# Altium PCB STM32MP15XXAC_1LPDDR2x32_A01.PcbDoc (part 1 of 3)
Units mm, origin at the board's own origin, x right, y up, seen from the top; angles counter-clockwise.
Board outline 89 x 120 mm, 6 copper layers (Top Layer, Signal Layer 1, Signal Layer 2, Signal Layer 3, Signal Layer 4, Bottom Layer), stack 1.556 mm thick; 87 components, 99 nets, 861 pads, 454 vias.
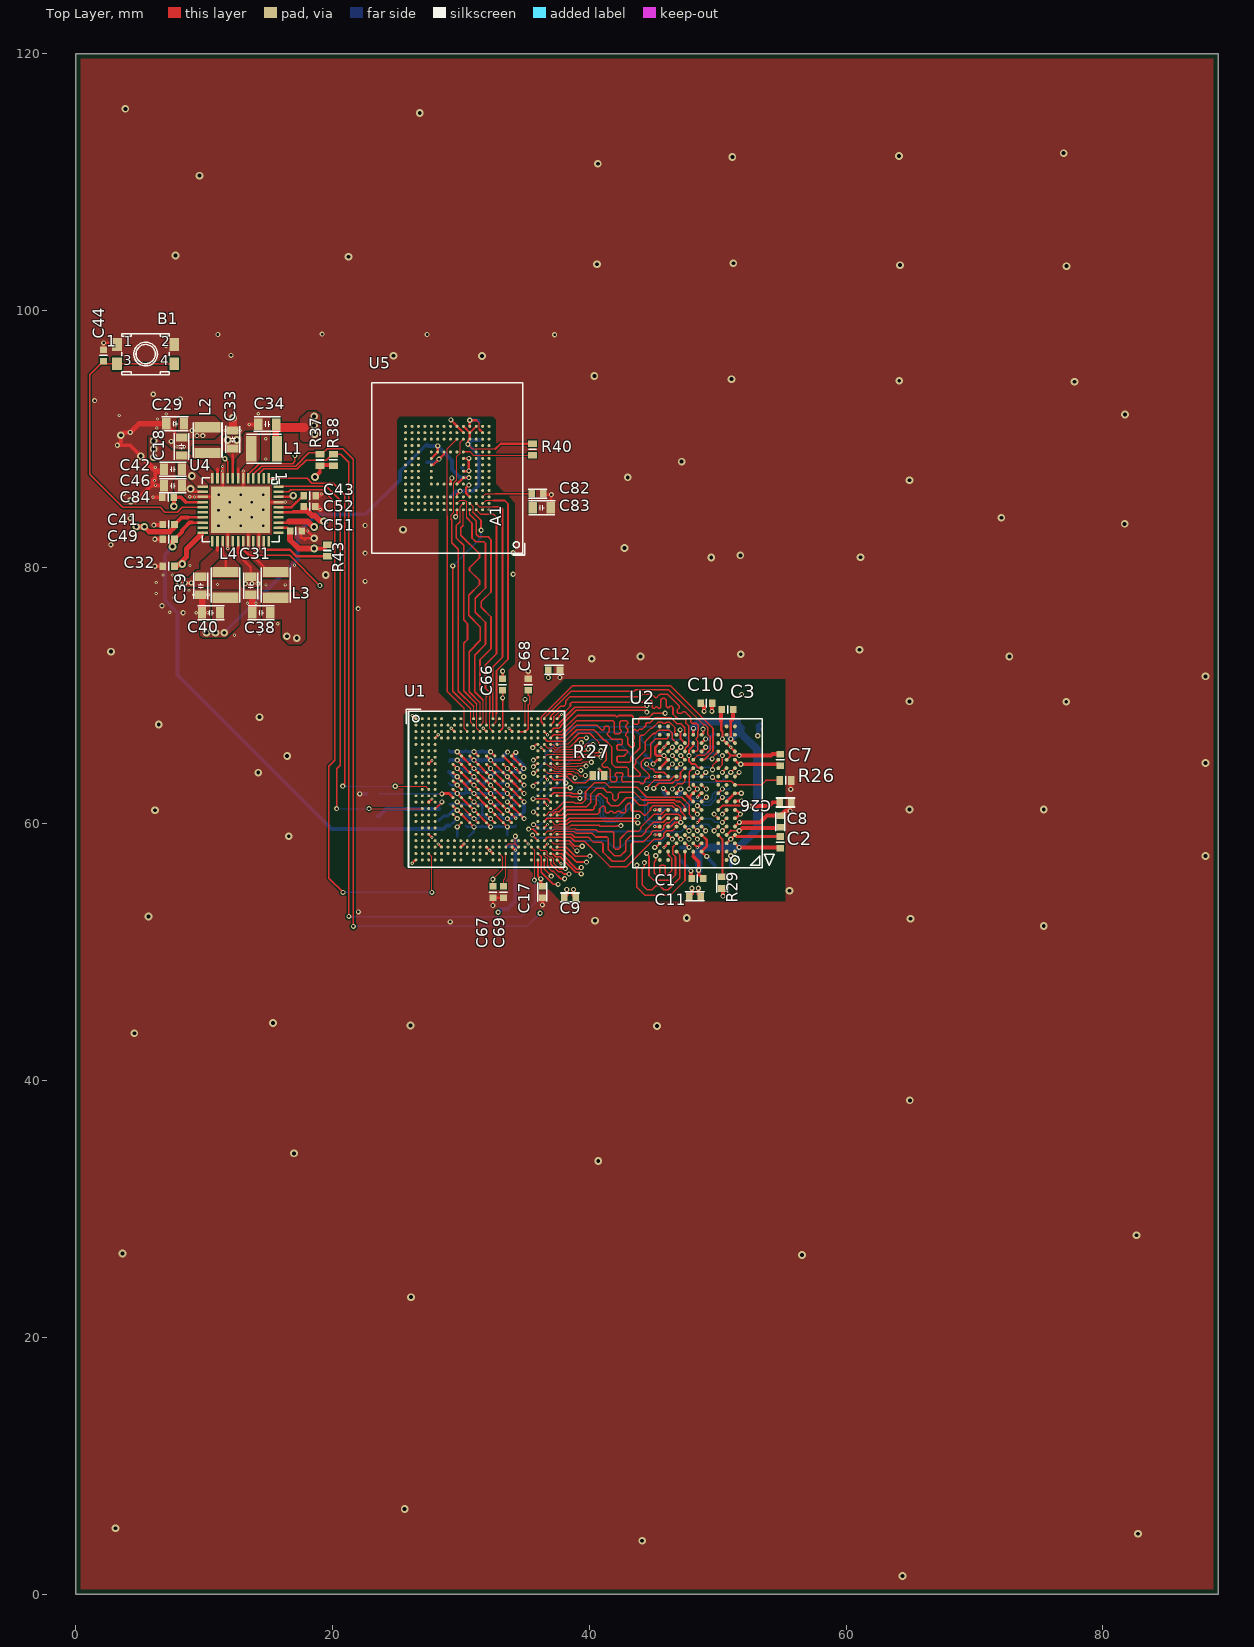
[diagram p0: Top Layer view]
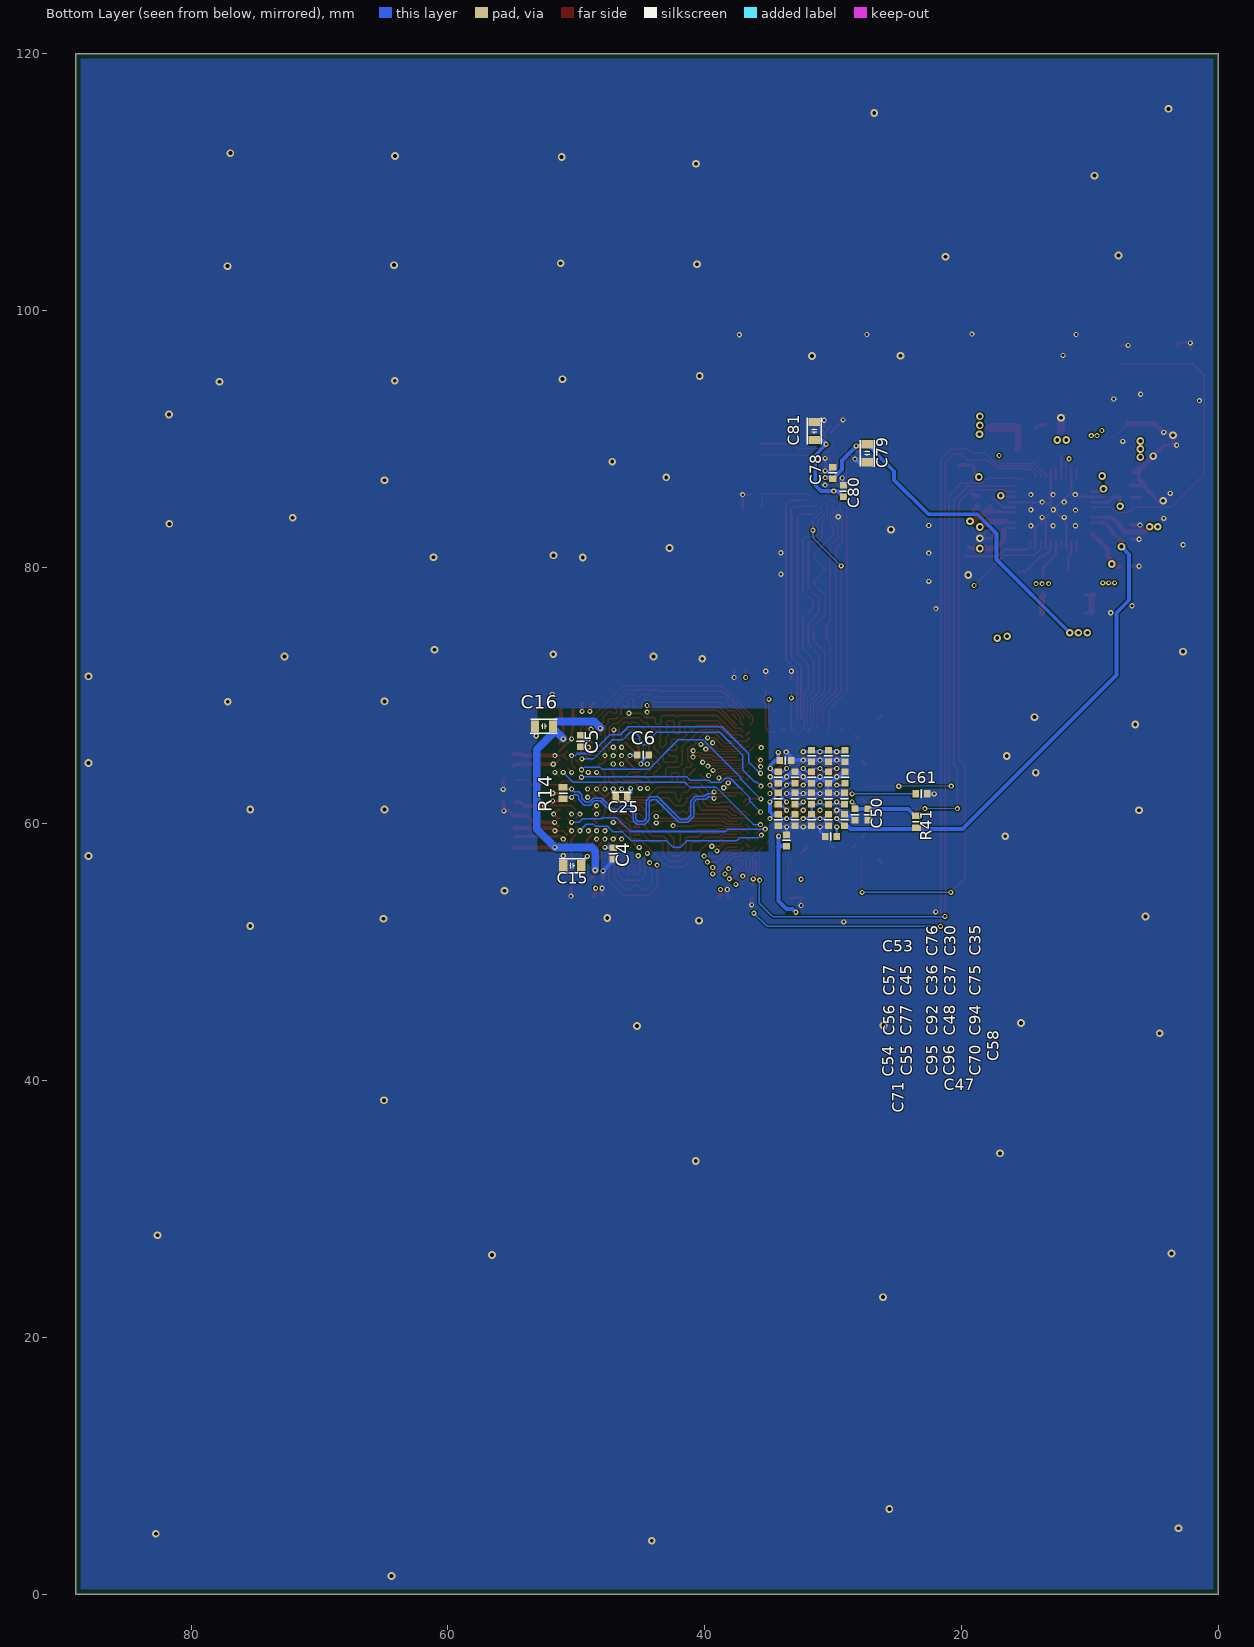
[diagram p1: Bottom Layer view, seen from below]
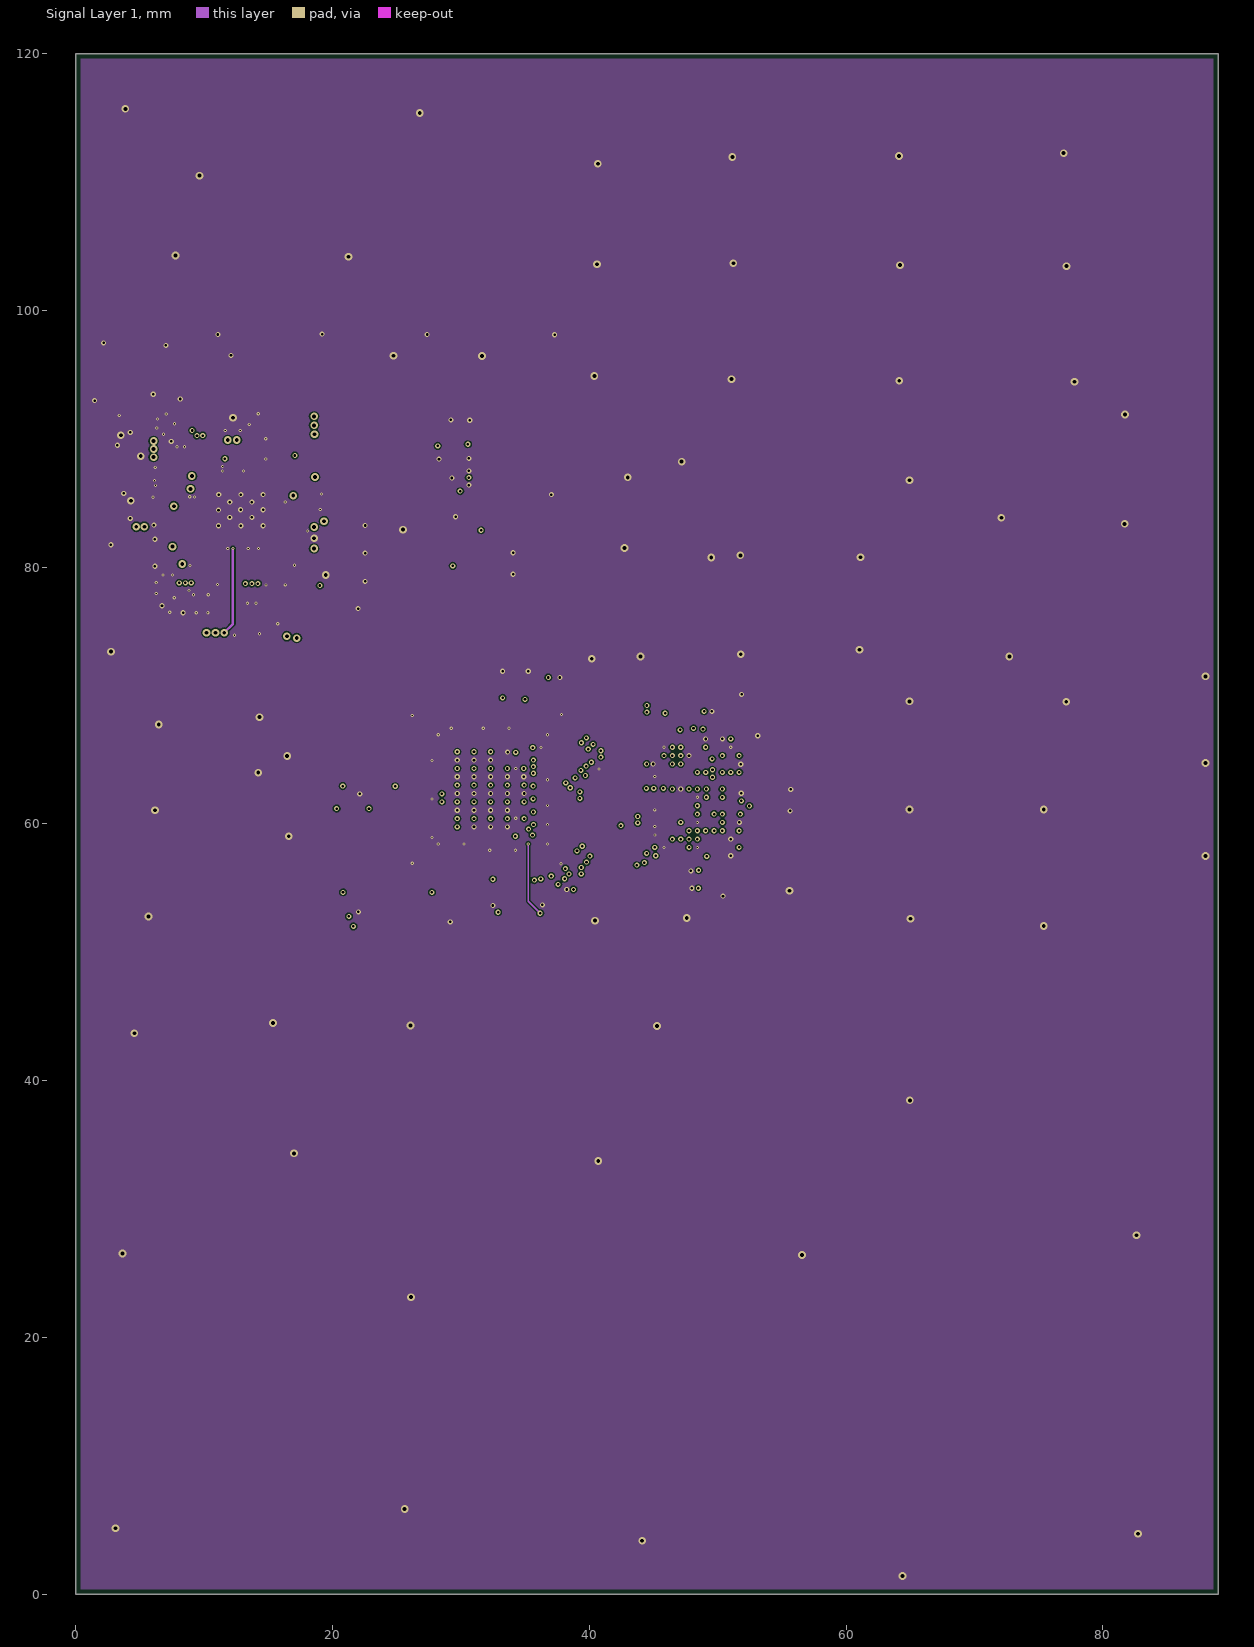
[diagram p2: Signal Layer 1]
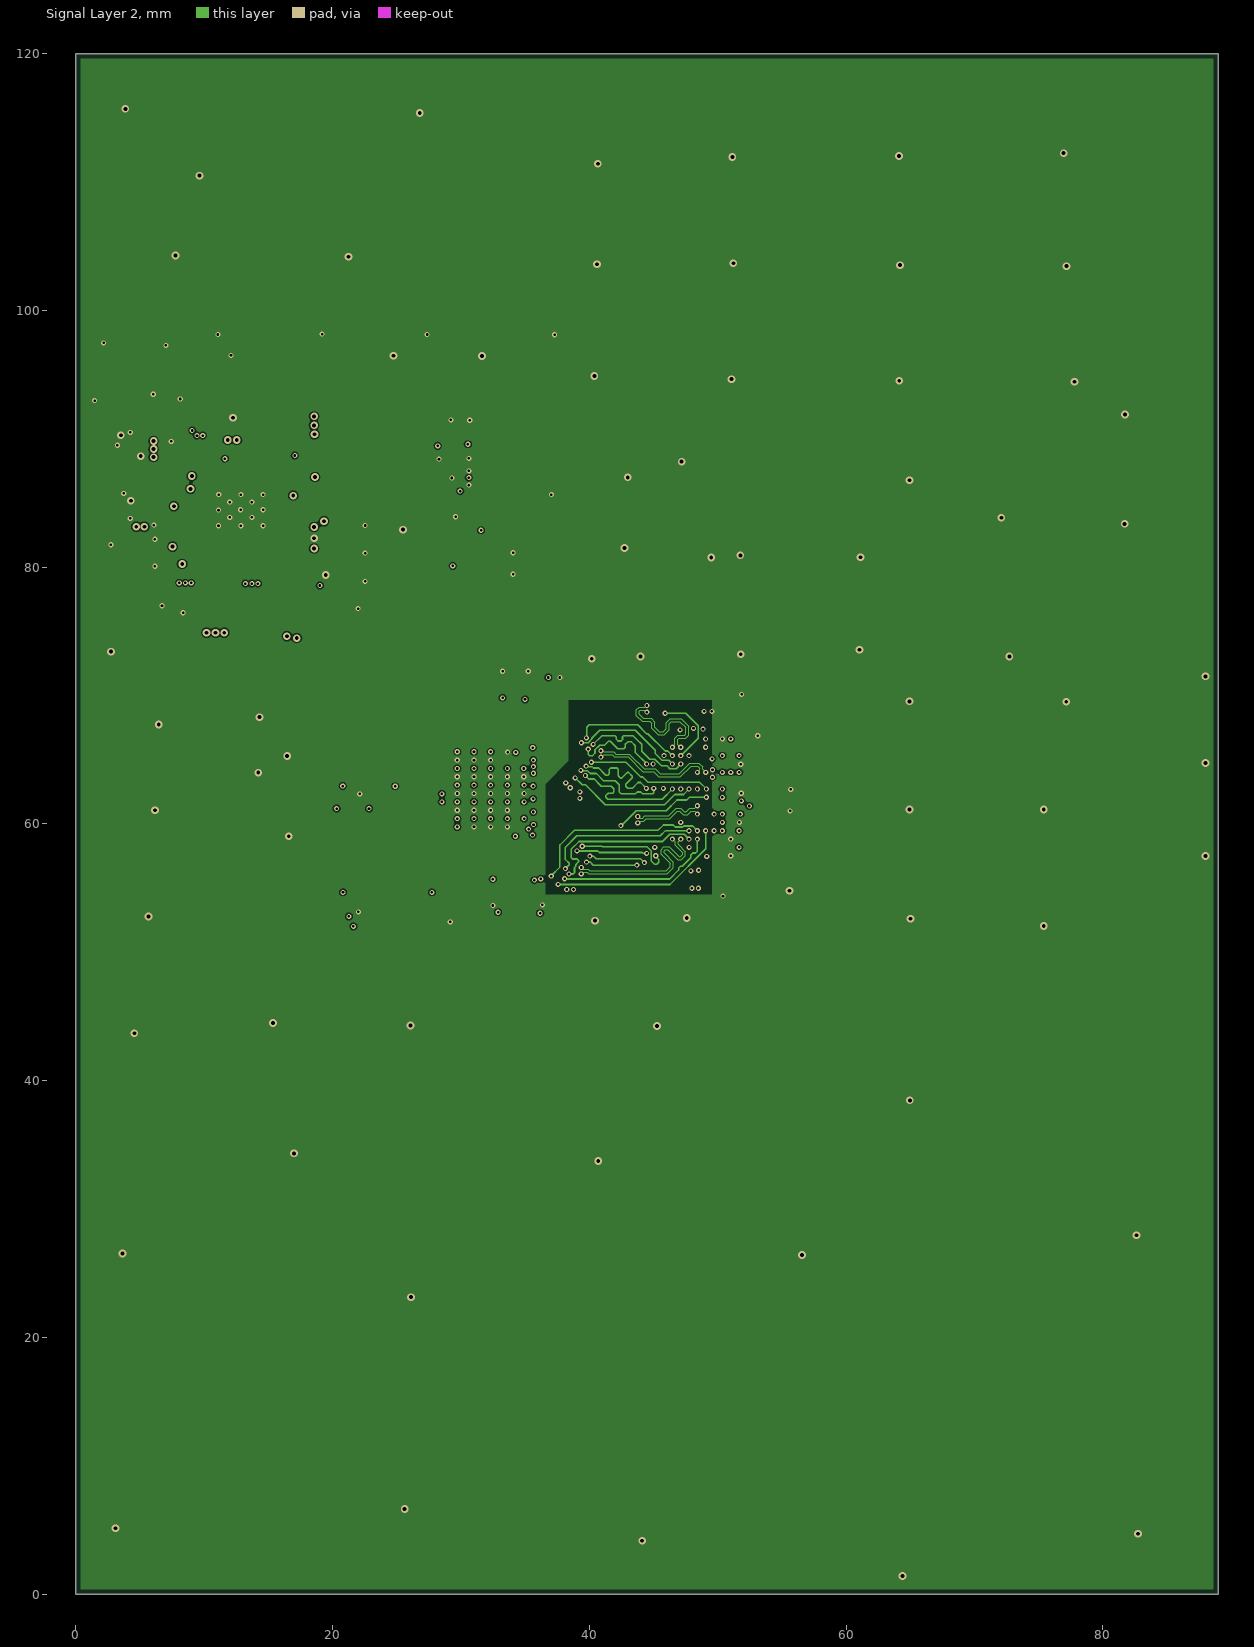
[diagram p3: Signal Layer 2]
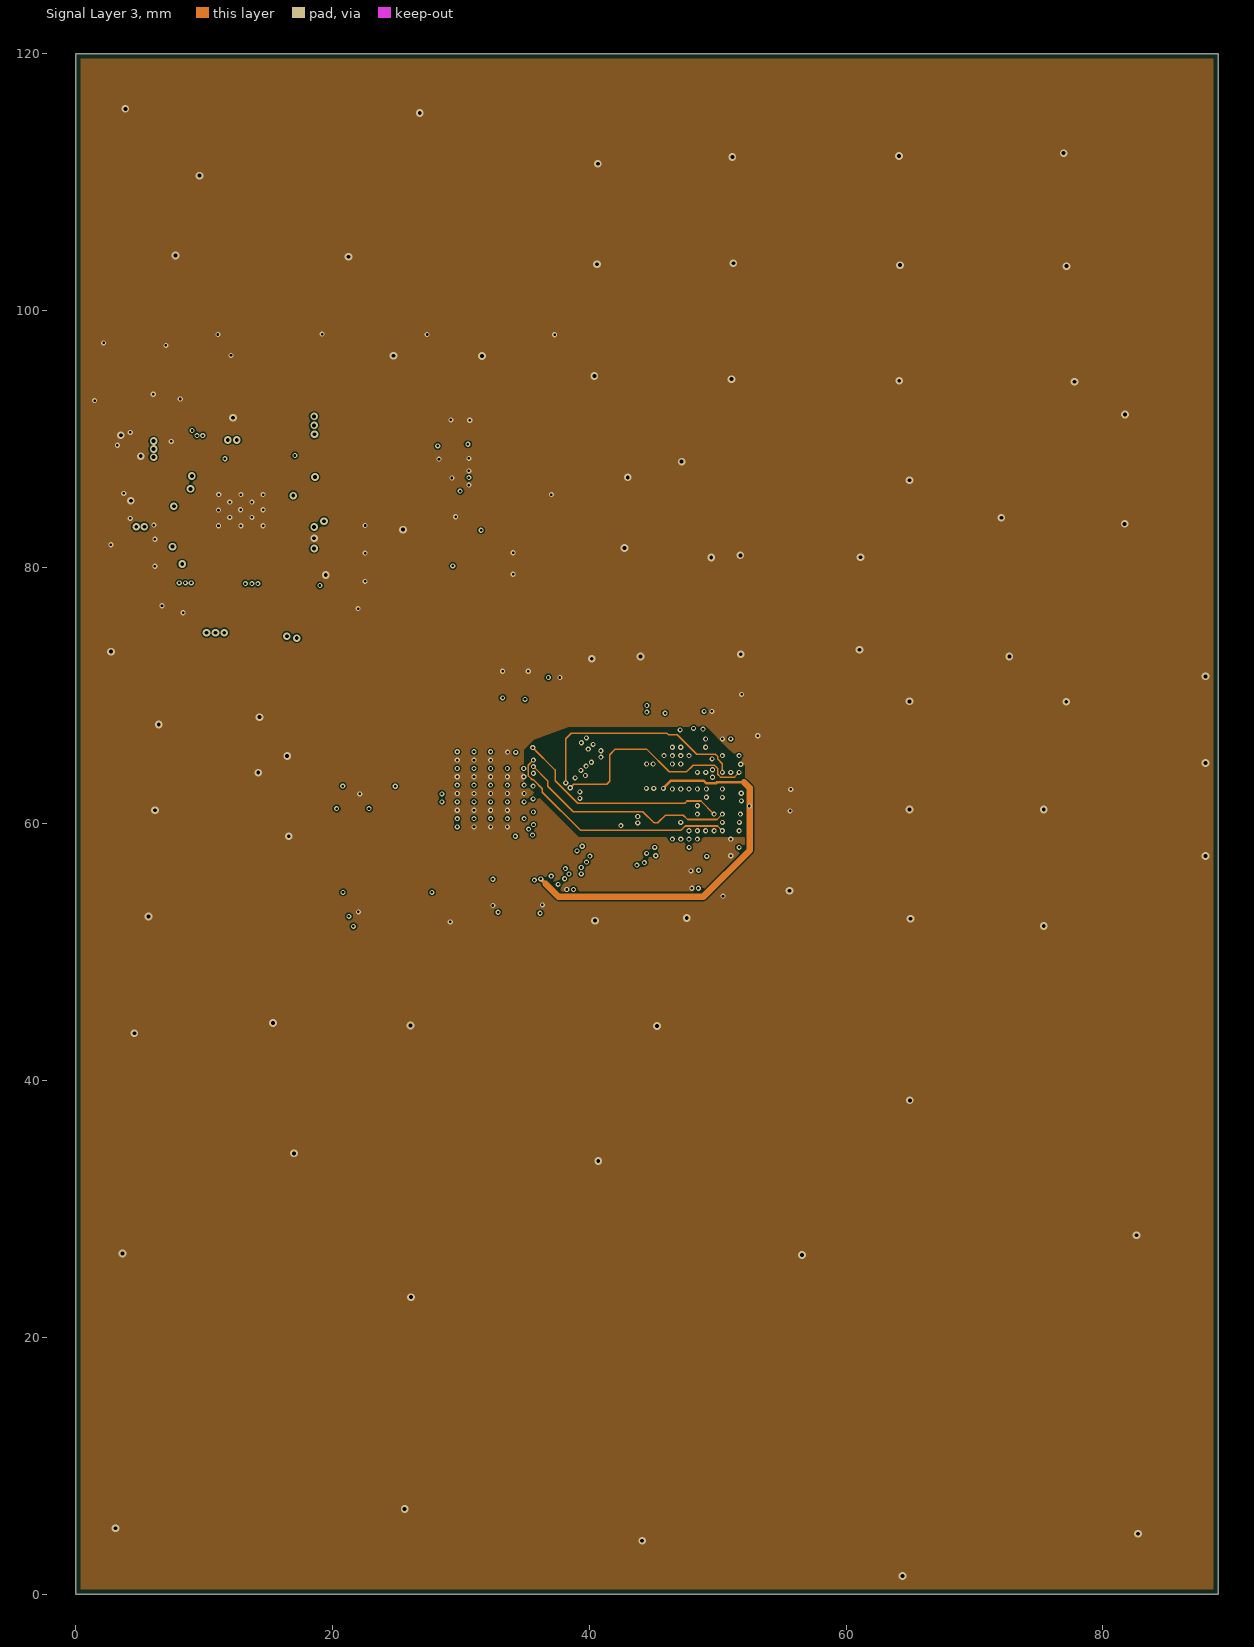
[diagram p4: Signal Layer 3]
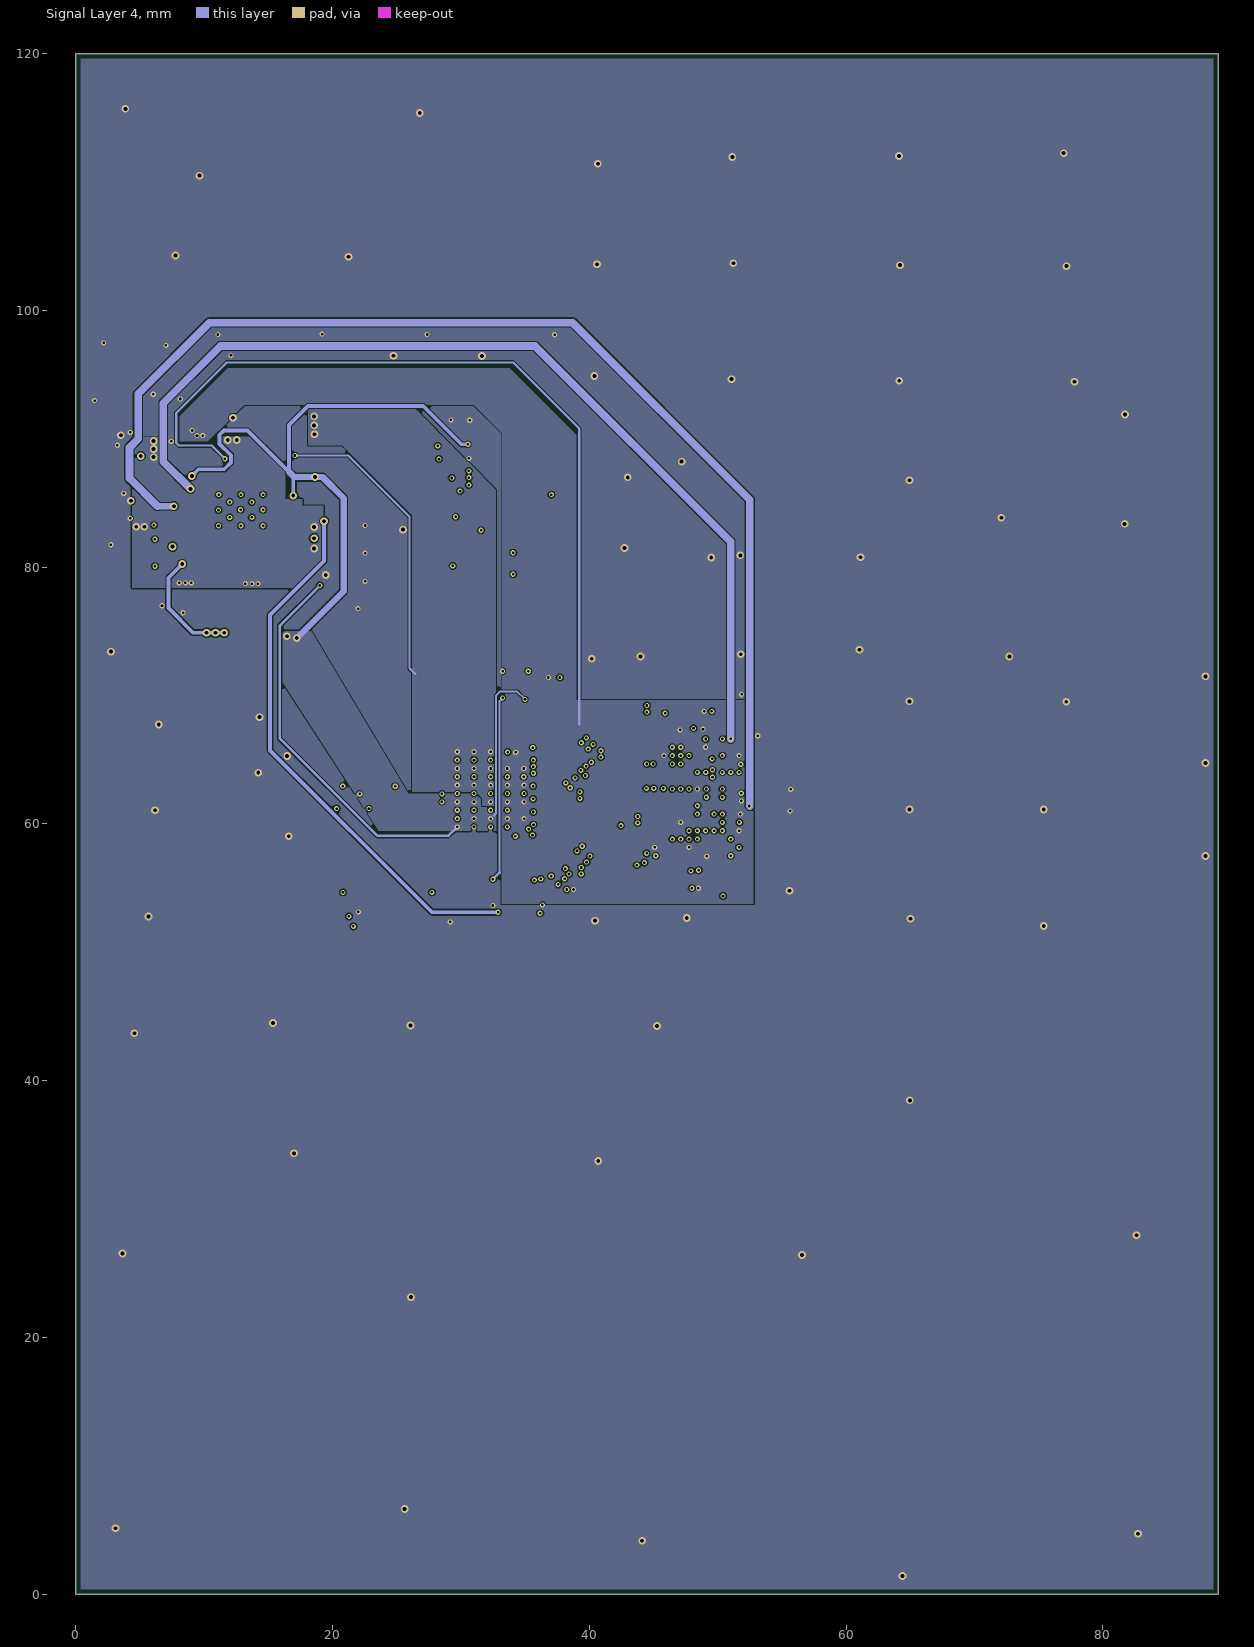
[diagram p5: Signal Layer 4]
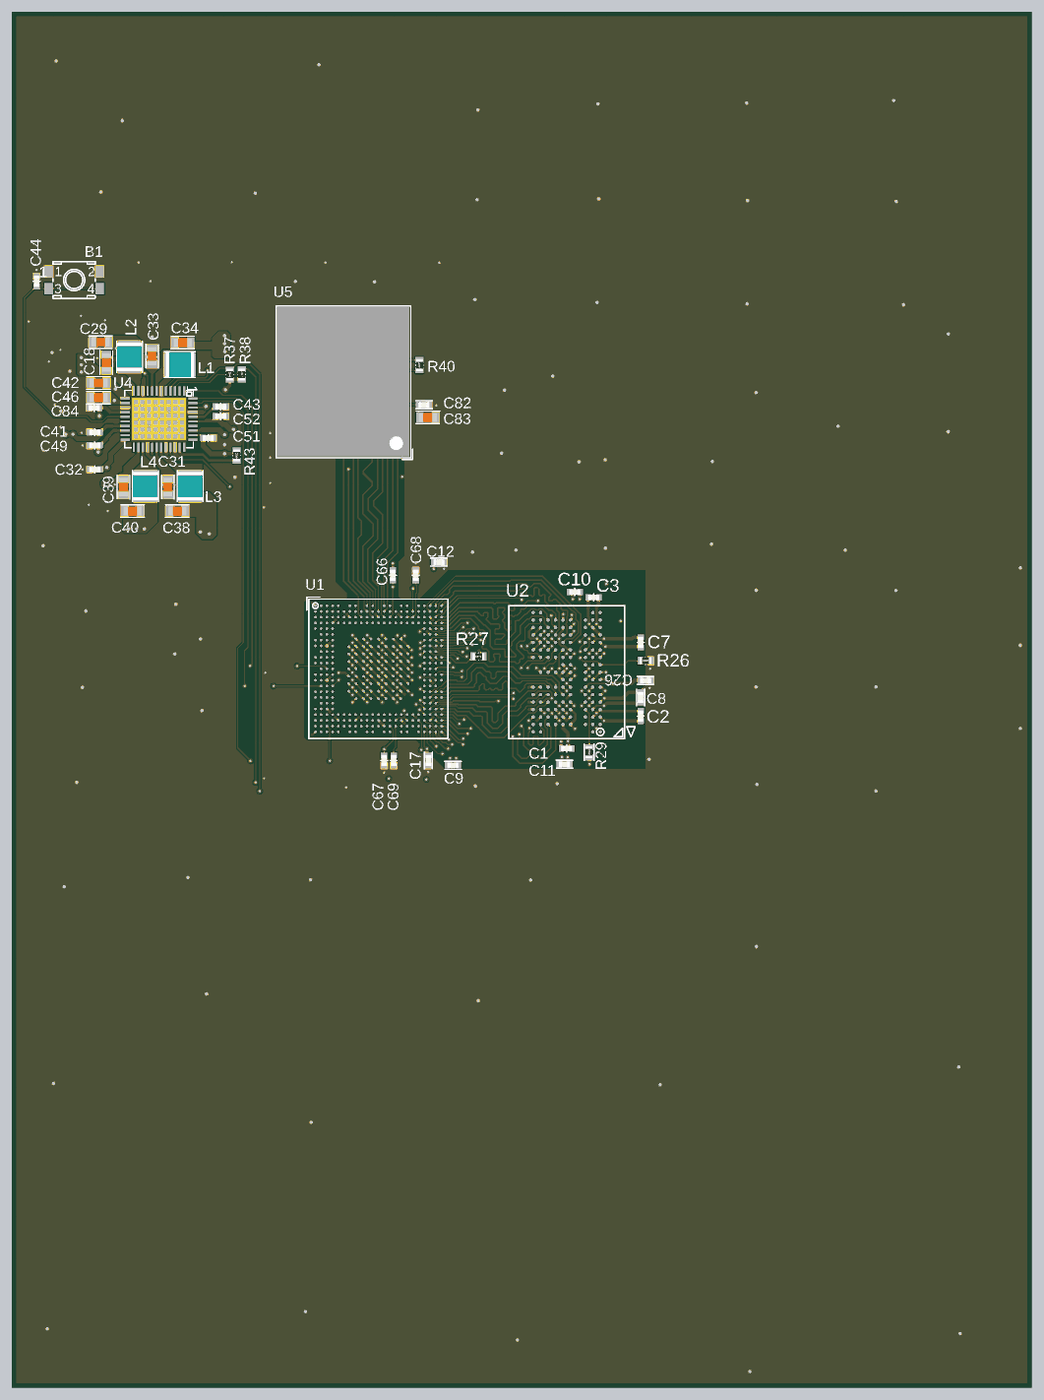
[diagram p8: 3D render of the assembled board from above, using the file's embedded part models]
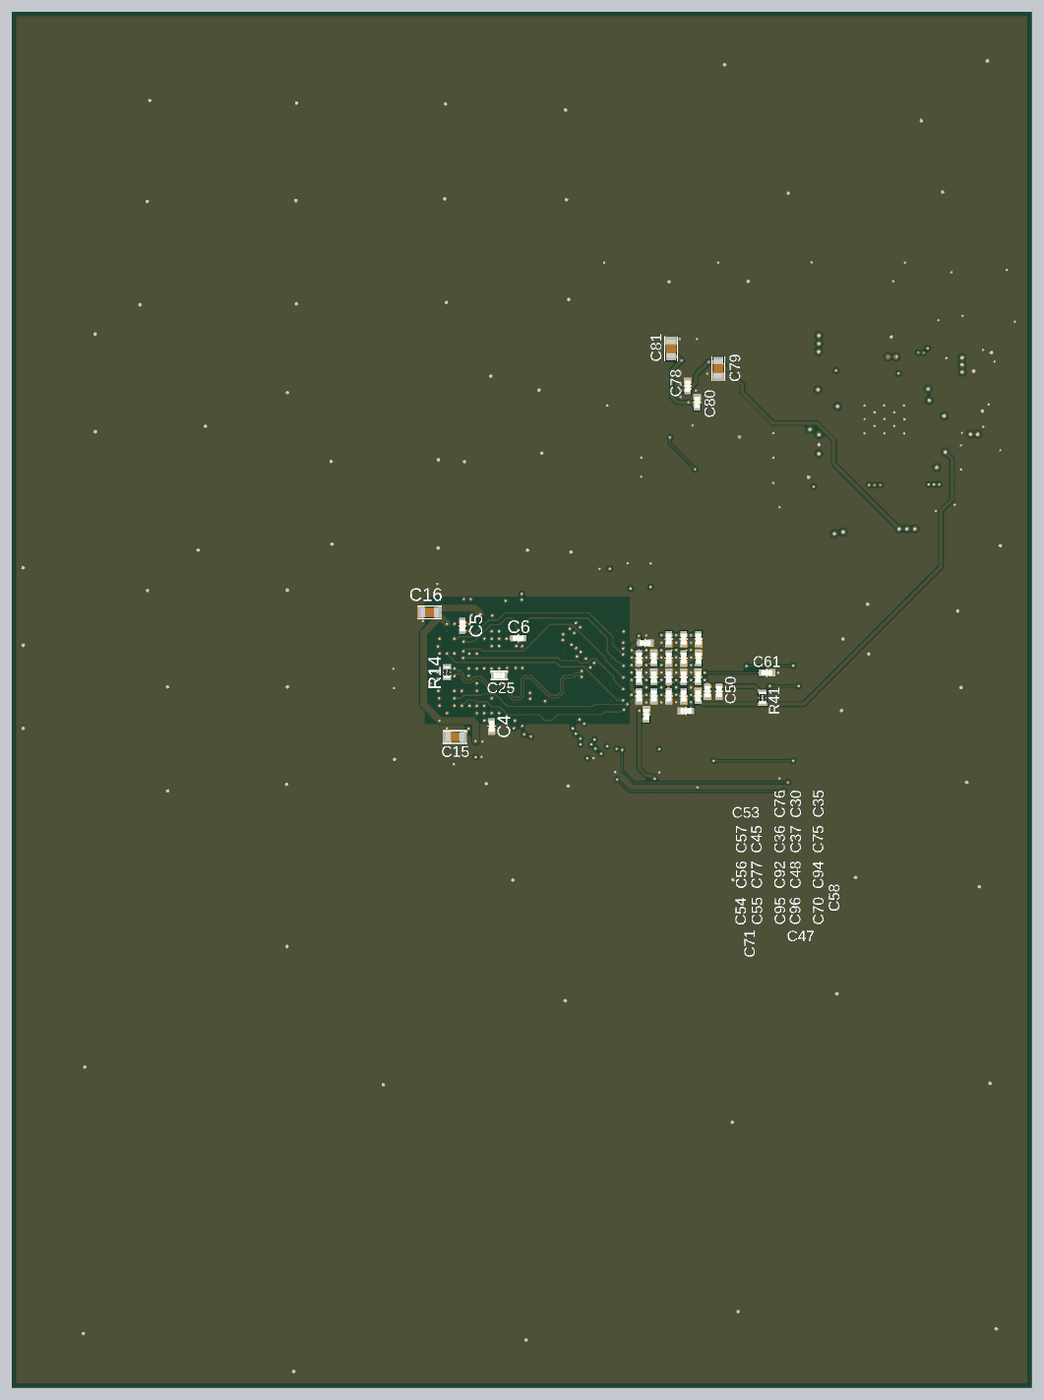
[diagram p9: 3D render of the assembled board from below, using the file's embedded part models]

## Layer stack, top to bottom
Top Solder: solder mask 0.0203, Solder Resist, Dk 3.5
Top Layer: signal copper 0.037
Dielectric 1: core 0.0986, FR-4, Dk 4.1
Signal Layer 1: signal copper 0.035
Dielectric 2: prepreg 0.13, Dk 4.25
Signal Layer 2: signal copper 0.035
Dielectric 3: core 0.885, Dk 4.25
Signal Layer 3: signal copper 0.035
Dielectric 4: prepreg 0.13, Dk 4.25
Signal Layer 4: signal copper 0.035
Dielectric 5: core 0.0986, Dk 4.1
Bottom Layer: signal copper 0.037
Bottom Solder: solder mask 0.0203, Solder Resist, Dk 3.5

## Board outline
89,120 89,0 0,0 0,120

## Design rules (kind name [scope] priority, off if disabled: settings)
BoardOutlineClearance [All] p1: gap=0.4 ignorepadtopadclearanceinfootprint=FALSE
Clearance diff [InNetClass('diff')] p1: gap=0.1 ignorepadtopadclearanceinfootprint=FALSE except(0: Arc-Hole Track-Hole SMDPad-Hole THPad-Hole Via-Hole Fill-Hole Poly-Hole Region-Hole Text-Hole; 0.08: Track-SMDPad; 0.15: Arc-Fill Track-Fill SMDPad-Fill THPad-Fill Via-Fill Fill-Fill; 0.2: Arc-THPad SMDPad-SMDPad SMDPad-THPad THPad-THPad)
Clearance [InNetClass('All Nets')] p2: gap=0.1 ignorepadtopadclearanceinfootprint=FALSE except(0: Arc-Hole Track-Hole SMDPad-Hole THPad-Hole Via-Hole Fill-Hole Poly-Hole Region-Hole Text-Hole; 0.08: Track-Track Track-SMDPad; 0.15: Arc-Fill Track-Fill SMDPad-Fill THPad-Fill Via-Fill Fill-Fill)
ComponentClearance [All] p1 off: gap=0.025 collisioncheckmode=3 verticalgap=2540 showdistances=TRUE
DiffPairsRouting [All] p1: maxlimit=0.14 minlimit=0.13 mostfreqgap=0.14 toplayer_maxgap=0.13 toplayer_prefgap=0.13 toplayer_minwidth=0.09 toplayer_maxwidth=0.13 toplayer_prefwidth=0.09 midlayer1_maxgap=0.13 midlayer1_prefgap=0.13 midlayer1_minwidth=0.09 midlayer1_maxwidth=0.13 midlayer1_prefwidth=0.09 midlayer2_mingap=0.14 midlayer2_minwidth=0.09 midlayer2_maxwidth=0.13 midlayer2_prefwidth=0.09 midlayer3_mingap=0.14 midlayer3_minwidth=0.09 midlayer3_maxwidth=0.13 midlayer3_prefwidth=0.09 midlayer4_maxgap=0.13 midlayer4_prefgap=0.13 midlayer4_minwidth=0.09 midlayer4_maxwidth=0.13 midlayer4_prefwidth=0.09 bottomlayer_maxgap=0.13 bottomlayer_prefgap=0.13 bottomlayer_minwidth=0.09 bottomlayer_maxwidth=0.13 bottomlayer_prefwidth=0.09 maxuncoupledlength=0.5
FanoutControl Fanout_BGA [IsBGA] p1: bgadir=Out bgaviamode=Closest fanoutstyle=Auto fanoutdirection=Alternating viagrid=0.025 // Fanout_BGA (Default Rule)
FanoutControl Fanout_LCC [IsLCC] p2: bgadir=Out bgaviamode=Closest fanoutstyle=Auto fanoutdirection=Alternating viagrid=0.025 // Fanout_LCC (Default Rule)
FanoutControl Fanout_SOIC [IsSOIC] p3: bgadir=Out bgaviamode=Closest fanoutstyle=Auto fanoutdirection=Alternating viagrid=0.025 // Fanout_SOIC (Default Rule)
FanoutControl Fanout_Small [(CompPinCount < 5)] p4: bgadir=Out bgaviamode=Closest fanoutstyle=Auto fanoutdirection=OutThenIn viagrid=0.025 // Fanout_Small (Default Rule)
FanoutControl Fanout_Default [All] p5: bgadir=Out bgaviamode=Closest fanoutstyle=Auto fanoutdirection=Alternating viagrid=0.025 // Fanout_Default (Default Rule)
Height [All] p1 off: minheight=0 maxheight=100 prefheight=0.5
HoleSize [All] p1: absolutevalues=TRUE maxlimit=10 minlimit=0.1 maxpercent=80.000 minpercent=20.000
HoleToHoleClearance [All] p1: gap=0.25 allowstackedmicrovias=TRUE
Length Length_SDMMC1 [InNetClass('NETC_SDMMC1')] p1: maxlimit=86 minlimit=81
MatchedLengths [All] p1: tolerance=25.4 checknetsindiffpair=FALSE checkdiffpairvsdiffpair=TRUE checkxsignals=TRUE checkothers=TRUE
MinimumSolderMaskSliver [All] p1: minsoldermaskwidth=0
PlaneClearance [All] p1: clearance=0.6
PlaneConnect [All] p1: planeconnectstyle=Direct reliefexpansion=0.508 reliefentries=4 reliefconductorwidth=0.254 reliefairgap=0.254
PolygonConnect PolygonConnect_notr [All vs (IsNamedPolygon('NO TR'))] p1: connectstyle=Direct reliefconductorwidth=0.254 reliefentries=4 polygonreliefangle="90 Angle" airgapwidth=0.254
PolygonConnect PolygonConnect_VTT_DDR [All vs IsNamedPolygon('VTT_DDR_BOT')] p2: connectstyle=Direct reliefconductorwidth=0.254 reliefentries=4 polygonreliefangle="45 Angle" airgapwidth=0.254
PolygonConnect [All] p3: connectstyle=Direct reliefconductorwidth=0.254 reliefentries=4 polygonreliefangle="45 Angle" airgapwidth=0.254
RoomDefinition U_1LPDDR2_32bits [InComponentClass('U_1LPDDR2_32bits')] p1: confinementstyle=ConfineIn formatcopy=TRUE lockcomponents=FALSE outline 90.122,1.441 127.399,1.441 127.399,7.441 90.122,7.441
RoomDefinition U_STM32_MPU_IOs [InComponentClass('U_STM32_MPU_IOs')] p2 off: confinementstyle=ConfineIn formatcopy=TRUE lockcomponents=FALSE outline 88.575,2.075 139.375,2.075 139.375,27.475 88.575,27.475
RoomDefinition U_Power_MPU [InComponentClass('U_Power_MPU')] p3 off: confinementstyle=ConfineIn formatcopy=TRUE lockcomponents=FALSE outline 87.122,16.916 100.898,16.916 100.898,22.892 87.122,22.892
RoomDefinition U_eMMC [InComponentClass('U_eMMC')] p4 off: confinementstyle=ConfineIn formatcopy=TRUE lockcomponents=FALSE outline 87.122,1.416 129.449,1.416 129.449,15.666 87.122,15.666
RoomDefinition U_Power_PMIC [InComponentClass('U_Power_PMIC')] p5 off: confinementstyle=ConfineIn formatcopy=TRUE lockcomponents=FALSE outline 87.122,8.666 203.578,8.666 203.578,17.666 87.122,17.666
RoutingVias RoutingVias_GND [InNetClass('GND')] p1: holewidth=0.3 width=0.6 viastyle="Through Hole" minholewidth=0.1 minwidth=0.25 maxholewidth=0.3 maxwidth=0.6
RoutingVias RoutingVias_ALIMS [InNetClass('ALIMS')] p2: holewidth=0.3 width=0.6 viastyle="Through Hole" minholewidth=0.2 minwidth=0.4 maxholewidth=0.3 maxwidth=0.6
RoutingVias [All] p3: holewidth=0.2 width=0.4 viastyle="Through Hole" minholewidth=0.1 minwidth=0.25 maxholewidth=0.3 maxwidth=0.6
SilkToSilkClearance [All] p1: silktosilkclearance=0
SilkToSolderMaskClearance [IsPad] p1: minsilkscreentomaskgap=0 clearancetoexposedcopper=TRUE
SolderMaskExpansion [All] p1: expansion=0.05
Width VDD2_DDR [InNet('VDD2_DDR')] p1: maxlimit=0.5 minlimit=0.1 preferedwidth=0.3
Width Width_VCORE [InNet('VDD_CORE')] p2: maxlimit=0.7 minlimit=0.1 preferedwidth=0.3 midlayer1_minwidth=0.12 midlayer2_minwidth=0.12 midlayer3_minwidth=0.12 midlayer4_minwidth=0.12 bottomlayer_minwidth=0.12 minimp=50.000000 maximp=50.000000 favimp=50.000000
Width Width_gnd [InNet('GND')] p3: maxlimit=0.7 minlimit=0.09 preferedwidth=0.3
Width [All] p4: maxlimit=0.6 minlimit=0.09 preferedwidth=0.12 midlayer1_minwidth=0.1 midlayer1_prefwidth=0.1 midlayer2_prefwidth=0.09 midlayer3_minwidth=0.127 midlayer3_prefwidth=0.127 midlayer4_minwidth=0.1 midlayer4_prefwidth=0.1 minimp=50.000000 maximp=50.000000 favimp=50.000000
15 further rules are at their usual default settings.

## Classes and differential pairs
component class U_1LPDDR2_32bits: C1 C2 C3 C4 C5 C6 C7 C8 C9 C10 C11 C12 C15 C16 C25 C26 R14 R26 R29 U2
net class eMMC_SDIO2_D[0..7]: eMMC_SDIO2_D0 eMMC_SDIO2_D1 eMMC_SDIO2_D2 eMMC_SDIO2_D3 eMMC_SDIO2_D4 eMMC_SDIO2_D5 eMMC_SDIO2_D6 eMMC_SDIO2_D7
component class U_STM32_MPU_IOs: C17 R27 R37 R38 U1
component class U_eMMC: C78 C79 C80 C81 C82 C83 R40 U5
component class U_Power_PMIC: B1 C18 C29 C31 C32 C33 C34 C38 C39 C40 C41 C42 C43 C44 C46 C49 C51 C52 C84 L1 L2 L3 L4 R43 U4
component class U_Power_MPU: C30 C35 C36 C37 C45 C47 C48 C50 C53 C54 C55 C56 C57 C58 C61 C66 C67 C68 C69 C70 C71 C75 C76 C77 C92 C94 C95 C96 R41
polygon class POLY_DIRECT_ALL: NETC906_2_L01_P192
differential pair class DIFF_DQS0: DDR_DQS0
differential pair class DIFF_DQS1: DDR_DQS1
differential pair class DIFF_CLK: DDR_CLK
differential pair DDR_DQS3: +DDR_DQS3_P -DDR_DQS3_N
differential pair DDR_DQS2: +DDR_DQS2_P -DDR_DQS2_N
differential pair DDR_DQS1: +DDR_DQS1_P -DDR_DQS1_N
differential pair DDR_DQS0: +DDR_DQS0_P -DDR_DQS0_N
differential pair DDR_CLK: +DDR_CLK_P -DDR_CLK_N

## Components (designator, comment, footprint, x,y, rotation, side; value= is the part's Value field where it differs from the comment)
B1 "" SWI_JIUBABA_C-TS-02H-2-5-B-V-T_R_BLUE 5.45,96.6 r0 top value=SW-PUSH-TS-02H-Blue
C1 "" C0402 48.425,55.75 r180 top value=100nF
C2 "" C0402 54.875,58.575 r90 top value=100nF
C3 "" C0402 50.775,68.925 r180 top value=100nF
C4 "" C0402 47.125,57.7 r270 bottom value=100nF
C5 "" C0402 49.675,66.45 r90 bottom value=100nF
C6 "" C0402 44.8,65.375 r180 bottom value=100nF
C7 "" C0402 54.875,65 r270 top value=100nF
C8 "" C0402 54.875,60.2 r90 top value=100nF
C9 "" C0402 38.5,54.275 r180 top value=100nF
C10 "" C0402 49.125,69.4 r0 top value=100nF
C11 "" C0402 48.225,54.375 r180 top value=100nF
C12 "" C0402 37.275,72 r0 top value=100nF
C15 "" C0603 50.325,56.75 r180 bottom value=10uF
C16 "" C0603 52.525,67.625 r180 bottom value=10uF
C17 "" C0402 36.35,54.7 r270 top value=100nF
C18 "" C0603 8.25,89.4 r270 top value=10uF
C25 "" C0402 46.475,62.125 r0 bottom value=100nF
C26 "" C0402 55.3,61.675 r0 top value=100nF
C29 "" C0603 7.75,91.175 r0 top value=22uF
C30 "" C0402 30.375,65.3 r90 bottom value=1uF
C31 "" C0603 13.625,78.55 r90 top value=10uF
C32 "" C0402 7.25,80.075 r0 top value=1uF
C33 "" C0603 12.25,89.95 r270 top value=10uF
C34 "" C0603 14.925,91.15 r0 top value=22uF
C35 "" C0402 29.075,65.3 r90 bottom value=1uF
C36 "" C0402 31.675,63.625 r90 bottom value=1uF
C37 "" C0402 30.375,63.625 r90 bottom value=1uF
C38 "" C0603 14.45,76.45 r0 top value=22uF
C39 "" C0603 9.75,78.55 r90 top value=10uF
C40 "" C0603 10.55,76.45 r0 top value=22uF
C41 "" C0402 7.25,83.325 r0 top value=1uF
C42 "" C0603 7.575,87.625 r0 top value=10uF
C43 "" C0402 18.234,85.562 r0 top value=4.7uF
C44 "" C0402 2.175,96.5 r270 top value=10nF
C45 "" C0402 32.975,63.625 r270 bottom value=1uF
C46 "" C0603 7.575,86.35 r0 top value=10uF
C47 "" C0402 30.175,59.025 r180 bottom value=1uF
C48 "" C0402 30.375,61.975 r270 bottom value=1uF
C49 "" C0402 7.25,82.175 r0 top value=4.7uF
C50 "" C0402 27.275,60.725 r90 bottom value=1uF
C51 "" C0402 17.15,82.825 r180 top value=4.7uF
C52 "" C0402 18.225,84.725 r180 top value=4.7uF
C53 "" C0402 33.725,64.95 r0 bottom value=1uF
C54 "" C0402 34.275,60.325 r90 bottom value=1uF
C55 "" C0402 32.975,60.325 r90 bottom value=1uF
C56 "" C0402 34.275,61.975 r90 bottom value=820pF
C57 "" C0402 34.275,63.625 r90 bottom value=820pF
C58 "" C0402 28.3,60.725 r90 bottom value=10nF
C61 "" C0402 23.125,62.35 r0 bottom value=100nF
C66 "" C0402 33.25,70.85 r270 top value=100nF
C67 "" C0402 32.5,54.7 r90 top value=2.2uF
C68 "" C0402 35.25,70.85 r270 top value=2.2uF
C69 "" C0402 33.325,54.7 r90 top value=2.2uF
C70 "" C0402 29.125,60.325 r270 bottom value=1uF
C71 "" C0402 33.625,58.725 r270 bottom value=100nF
C75 "" C0402 29.075,63.625 r270 bottom value=1uF
C76 "" C0402 31.675,65.3 r90 bottom value=1uF
C77 "" C0402 32.975,61.975 r270 bottom value=1uF
C78 "" C0402 30.025,87.35 r270 bottom value=100nF
C79 "" C0603 27.35,88.875 r90 bottom value=2.2uF
C80 "" C0402 29.2,85.925 r270 bottom value=100nF
C81 "" C0603 31.475,90.6 r270 bottom value=2.2uF
C82 "" C0402 35.975,85.725 r180 top value=100nF
C83 "" C0603 36.3,84.625 r180 top value=2.2uF
C84 "" C0402 7.2,85.45 r0 top value=1uF
C92 "" C0402 31.675,61.975 r270 bottom value=1uF
C94 "" C0402 29.125,61.975 r270 bottom value=1uF
C95 "" C0402 31.675,60.325 r90 bottom value=1uF
C96 "" C0402 30.375,60.325 r90 bottom value=1uF
L1 "" IND_2520_TOKO_DFE252012P 14.675,89.225 r0 top value=1uH
L2 "" IND_2520_TOKO_DFE252012P 10.275,89.9 r90 top value=1uH
L3 "" IND_2520_TOKO_DFE252012P 15.575,78.625 r270 top value=1uH
L4 "" IND_2520_TOKO_DFE252012P 11.675,78.625 r270 top value=1uH
R14 "" R0402 51.025,62.4 r270 bottom value=100R
R26 "" R0402 55.3,63.4 r180 top value=10K
R27 "" R0402 40.725,63.775 r0 top value="240R 1%"
R29 "" R0402 50.375,55.425 r90 top value="240R 1%"
R37 "" R0402 19.025,88.35 r90 top value=1K5
R38 "" R0402 20.074,88.363 r90 top value=1K5
R40 "" R0402 35.575,89.175 r90 top value=10K
R41 "" R0402 23.5,60.175 r90 bottom value=0R
R43 "" R0402 19.625,81.3 r90 top value=47K
U1 "" ICC_TFBGA361_12X12_STM32MP157CAC3_P050-065 32,62.7 r0 top locked value=STM32MP157CAC3
U2 "" ICC_WFBGA134_SDP-SAC302_10X11P5_P065 48.425,62.4 r180 top locked value=EDB4432BBBJ-1D-F-R
U4 "" ICC_WFQFN44-EPAD_5X6_P040 12.85,84.475 r270 top value=STPMU1A
U5 "" ICC_P-WFBGA153_13X11P5_P050 28.95,87.725 r90 top locked value=THGBMDG5D1LBAIL

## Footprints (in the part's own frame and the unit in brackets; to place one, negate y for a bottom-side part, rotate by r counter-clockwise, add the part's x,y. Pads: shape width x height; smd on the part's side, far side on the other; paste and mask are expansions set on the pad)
C0402 [mm]
  rect 0.51x0.56 smd mask+0.05: 1(-0.45,0) 2(0.45,0)
  silkscreen extent 0,-0.3 0,0.3, body extent -0.5,-0.3 0.5,0.3, height 0.4
C0603 [mm]
  rect 0.64x0.89 smd mask+0.05: 1(-0.7,0) 2(0.7,0)
  silkscreen extent -1.05,-0.55 1.02,0.55, body extent -0.9,-0.5 0.9,0.5, height 1.4
ICC_P-WFBGA153_13X11P5_P050 [mm]
  round 0.23 smd mask+0.05: A1(-3.25,-3.25) A2(-3.25,-2.75) A3(-3.25,-2.25) A4(-3.25,-1.75) A5(-3.25,-1.25) A6(-3.25,-0.75) A7(-3.25,-0.25) A8(-3.25,0.25) A9(-3.25,0.75) A10(-3.25,1.25) A11(-3.25,1.75) A12(-3.25,2.25) A13(-3.25,2.75) A14(-3.25,3.25) B1(-2.75,-3.25) B2(-2.75,-2.75) B3(-2.75,-2.25) B4(-2.75,-1.75) B5(-2.75,-1.25) B6(-2.75,-0.75) B7(-2.75,-0.25) B8(-2.75,0.25) B9(-2.75,0.75) B10(-2.75,1.25) B11(-2.75,1.75) B12(-2.75,2.25) B13(-2.75,2.75) B14(-2.75,3.25) C1(-2.25,-3.25) C2(-2.25,-2.75) C3(-2.25,-2.25) C4(-2.25,-1.75) C5(-2.25,-1.25) C6(-2.25,-0.75) C7(-2.25,-0.25) C8(-2.25,0.25) C9(-2.25,0.75) C10(-2.25,1.25) C11(-2.25,1.75) C12(-2.25,2.25) C13(-2.25,2.75) C14(-2.25,3.25) D1(-1.75,-3.25) D2(-1.75,-2.75) D3(-1.75,-2.25) D4(-1.75,-1.75) D12(-1.75,2.25) D13(-1.75,2.75) D14(-1.75,3.25) E1(-1.25,-3.25) E2(-1.25,-2.75) E3(-1.25,-2.25) E5(-1.25,-1.25) E6(-1.25,-0.75) E7(-1.25,-0.25) E8(-1.25,0.25) E9(-1.25,0.75) E10(-1.25,1.25) E12(-1.25,2.25) E13(-1.25,2.75) E14(-1.25,3.25) F1(-0.75,-3.25) F2(-0.75,-2.75) F3(-0.75,-2.25) F5(-0.75,-1.25) F10(-0.75,1.25) F12(-0.75,2.25) F13(-0.75,2.75) F14(-0.75,3.25) G1(-0.25,-3.25) G2(-0.25,-2.75) G3(-0.25,-2.25) G5(-0.25,-1.25) G10(-0.25,1.25) G12(-0.25,2.25) G13(-0.25,2.75) G14(-0.25,3.25) H1(0.25,-3.25) H2(0.25,-2.75) H3(0.25,-2.25) H5(0.25,-1.25) H10(0.25,1.25) H12(0.25,2.25) H13(0.25,2.75) H14(0.25,3.25) J1(0.75,-3.25) J2(0.75,-2.75) J3(0.75,-2.25) J5(0.75,-1.25) J10(0.75,1.25) J12(0.75,2.25) J13(0.75,2.75) J14(0.75,3.25) K1(1.25,-3.25) K2(1.25,-2.75) K3(1.25,-2.25) K5(1.25,-1.25) K6(1.25,-0.75) K7(1.25,-0.25) K8(1.25,0.25) K9(1.25,0.75) K10(1.25,1.25) K12(1.25,2.25) K13(1.25,2.75) K14(1.25,3.25) L1(1.75,-3.25) L2(1.75,-2.75) L3(1.75,-2.25) L12(1.75,2.25) L13(1.75,2.75) L14(1.75,3.25) M1(2.25,-3.25) M2(2.25,-2.75) M3(2.25,-2.25) M4(2.25,-1.75) M5(2.25,-1.25) M6(2.25,-0.75) M7(2.25,-0.25) M8(2.25,0.25) M9(2.25,0.75) M10(2.25,1.25) M11(2.25,1.75) M12(2.25,2.25) M13(2.25,2.75) M14(2.25,3.25) N1(2.75,-3.25) N2(2.75,-2.75) N3(2.75,-2.25) N4(2.75,-1.75) N5(2.75,-1.25) N6(2.75,-0.75) N7(2.75,-0.25) N8(2.75,0.25) N9(2.75,0.75) N10(2.75,1.25) N11(2.75,1.75) N12(2.75,2.25) N13(2.75,2.75) N14(2.75,3.25) P1(3.25,-3.25) P2(3.25,-2.75) P3(3.25,-2.25) P4(3.25,-1.75) P5(3.25,-1.25) P6(3.25,-0.75) P7(3.25,-0.25) P8(3.25,0.25) P9(3.25,0.75) P10(3.25,1.25) P11(3.25,1.75) P12(3.25,2.25) P13(3.25,2.75) P14(3.25,3.25)
  silkscreen extent -6.78,-6.02 6.63,5.87, body extent -6.55,-5.8 6.55,5.8, height 1
ICC_TFBGA361_12X12_STM32MP157CAC3_P050-065 [mm] "IPC"
  round 0.23 smd mask+0.05: 1A2(-1.95,2.6) 1A3(-1.3,2.6) 1A4(-0.65,2.6) 1A5(0,2.6) 1A6(0.65,2.6) 1A7(1.3,2.6) 1A8(1.95,2.6) 1B1(-2.6,1.95) 1B2(-1.95,1.95) 1B3(-1.3,1.95) 1B4(-0.65,1.95) 1B5(0,1.95) 1B6(0.65,1.95) 1B7(1.3,1.95) 1B8(1.95,1.95) 1B9(2.6,1.95) 1C1(-2.6,1.3) 1C2(-1.95,1.3) 1C3(-1.3,1.3) 1C4(-0.65,1.3) 1C5(0,1.3) 1C6(0.65,1.3) 1C7(1.3,1.3) 1C8(1.95,1.3) 1C9(2.6,1.3) 1D1(-2.6,0.65) 1D2(-1.95,0.65) 1D3(-1.3,0.65) 1D4(-0.65,0.65) 1D5(0,0.65) 1D6(0.65,0.65) 1D7(1.3,0.65) 1D8(1.95,0.65) 1D9(2.6,0.65) 1E1(-2.6,0) 1E2(-1.95,0) 1E3(-1.3,0) 1E4(-0.65,0) 1E5(0,0) 1E6(0.65,0) 1E7(1.3,0) 1E8(1.95,0) 1E9(2.6,0) 1F1(-2.6,-0.65) 1F2(-1.95,-0.65) 1F3(-1.3,-0.65) 1F4(-0.65,-0.65) 1F5(0,-0.65) 1F6(0.65,-0.65) 1F7(1.3,-0.65) 1F8(1.95,-0.65) 1F9(2.6,-0.65) 1G1(-2.6,-1.3) 1G2(-1.95,-1.3) 1G3(-1.3,-1.3) 1G4(-0.65,-1.3) 1G5(0,-1.3) 1G6(0.65,-1.3) 1G7(1.3,-1.3) 1G8(1.95,-1.3) 1G9(2.6,-1.3) 1H1(-2.6,-1.95) 1H2(-1.95,-1.95) 1H3(-1.3,-1.95) 1H4(-0.65,-1.95) 1H5(0,-1.95) 1H6(0.65,-1.95) 1H7(1.3,-1.95) 1H8(1.95,-1.95) 1H9(2.6,-1.95) 1J2(-1.95,-2.6) 1J3(-1.3,-2.6) 1J4(-0.65,-2.6) 1J5(0,-2.6) 1J6(0.65,-2.6) 1J7(1.3,-2.6) 1J8(1.95,-2.6) A1(-5.5,5.5) A2(-5,5.5) A3(-4.5,5.5) A4(-4,5.5) A5(-3.5,5.5) A7(-2.5,5.5) A8(-2,5.5) A10(-1,5.5) A11(-0.5,5.5) A13(0.5,5.5) A14(1,5.5) A16(2,5.5) A17(2.5,5.5) A19(3.5,5.5) A20(4,5.5) A21(4.5,5.5) A22(5,5.5) A23(5.5,5.5) AA1(-5.5,-4.5) AA2(-5,-4.5) AA3(-4.5,-4.5) AA4(-4,-4.5) AA5(-3.5,-4.5) AA6(-3,-4.5) AA7(-2.5,-4.5) AA8(-2,-4.5) AA9(-1.5,-4.5) AA10(-1,-4.5) AA11(-0.5,-4.5) AA12(0,-4.5) AA13(0.5,-4.5) AA14(1,-4.5) AA15(1.5,-4.5) AA16(2,-4.5) AA17(2.5,-4.5) AA18(3,-4.5) AA19(3.5,-4.5) AA20(4,-4.5) AA21(4.5,-4.5) AA22(5,-4.5) AA23(5.5,-4.5) AB1(-5.5,-5) AB2(-5,-5) AB3(-4.5,-5) AB4(-4,-5) AB5(-3.5,-5) AB6(-3,-5) AB7(-2.5,-5) AB8(-2,-5) AB9(-1.5,-5) AB10(-1,-5) AB11(-0.5,-5) AB12(0,-5) AB13(0.5,-5) AB14(1,-5) AB15(1.5,-5) AB16(2,-5) AB17(2.5,-5) AB18(3,-5) AB19(3.5,-5) AB20(4,-5) AB21(4.5,-5) AB22(5,-5) AB23(5.5,-5) AC1(-5.5,-5.5) AC2(-5,-5.5) AC3(-4.5,-5.5) AC4(-4,-5.5) AC5(-3.5,-5.5) AC7(-2.5,-5.5) AC8(-2,-5.5) AC10(-1,-5.5) AC11(-0.5,-5.5) AC13(0.5,-5.5) AC14(1,-5.5) AC16(2,-5.5) AC17(2.5,-5.5) AC19(3.5,-5.5) AC20(4,-5.5) AC21(4.5,-5.5) AC22(5,-5.5) AC23(5.5,-5.5) B1(-5.5,5) B2(-5,5) B3(-4.5,5) B4(-4,5) B5(-3.5,5) B6(-3,5) B7(-2.5,5) B8(-2,5) B9(-1.5,5) B10(-1,5) B11(-0.5,5) B12(0,5) B13(0.5,5) B14(1,5) B15(1.5,5) B16(2,5) B17(2.5,5) B18(3,5) B19(3.5,5) B20(4,5) B21(4.5,5) B22(5,5) B23(5.5,5) C1(-5.5,4.5) C2(-5,4.5) C3(-4.5,4.5) C4(-4,4.5) C5(-3.5,4.5) C6(-3,4.5) C7(-2.5,4.5) C8(-2,4.5) C9(-1.5,4.5) C10(-1,4.5) C11(-0.5,4.5) C12(0,4.5) C13(0.5,4.5) C14(1,4.5) C15(1.5,4.5) C16(2,4.5) C17(2.5,4.5) C18(3,4.5) C19(3.5,4.5) C20(4,4.5) C21(4.5,4.5) C22(5,4.5) C23(5.5,4.5) D1(-5.5,4) D2(-5,4) D3(-4.5,4) D4(-4,4) D5(-3.5,4) D6(-3,4) D7(-2.5,4) D8(-2,4) D9(-1.5,4) D10(-1,4) D11(-0.5,4) D12(0,4) D13(0.5,4) D14(1,4) D15(1.5,4) D16(2,4) D17(2.5,4) D18(3,4) D19(3.5,4) D20(4,4) D21(4.5,4) D22(5,4) D23(5.5,4) E1(-5.5,3.5) E2(-5,3.5) E3(-4.5,3.5) E4(-4,3.5) E20(4,3.5) E21(4.5,3.5) E22(5,3.5) E23(5.5,3.5) F2(-5,3) F3(-4.5,3) F4(-4,3) F20(4,3) F21(4.5,3) F22(5,3) G1(-5.5,2.5) G2(-5,2.5) G3(-4.5,2.5) G4(-4,2.5) G20(4,2.5) G21(4.5,2.5) G22(5,2.5) G23(5.5,2.5) H1(-5.5,2) H2(-5,2) H3(-4.5,2) H4(-4,2) H20(4,2) H21(4.5,2) H22(5,2) H23(5.5,2) J2(-5,1.5) J3(-4.5,1.5) J4(-4,1.5) J20(4,1.5) J21(4.5,1.5) J22(5,1.5) K1(-5.5,1) K2(-5,1) K3(-4.5,1) K4(-4,1) K20(4,1) K21(4.5,1) K22(5,1) K23(5.5,1) L1(-5.5,0.5) L2(-5,0.5) L3(-4.5,0.5) L4(-4,0.5) L20(4,0.5) L21(4.5,0.5) L22(5,0.5) L23(5.5,0.5) M2(-5,0) M3(-4.5,0) M4(-4,0) M20(4,0) M21(4.5,0) M22(5,0) N1(-5.5,-0.5) N2(-5,-0.5) N3(-4.5,-0.5) N4(-4,-0.5) N20(4,-0.5) N21(4.5,-0.5) N22(5,-0.5) N23(5.5,-0.5) P1(-5.5,-1) P2(-5,-1) P3(-4.5,-1) P4(-4,-1) P20(4,-1) P21(4.5,-1) P22(5,-1) P23(5.5,-1) R2(-5,-1.5) R3(-4.5,-1.5) R4(-4,-1.5) R20(4,-1.5) R21(4.5,-1.5) R22(5,-1.5) T1(-5.5,-2) T2(-5,-2) T3(-4.5,-2) T4(-4,-2) T20(4,-2) T21(4.5,-2) T22(5,-2) T23(5.5,-2) U1(-5.5,-2.5) U2(-5,-2.5) U3(-4.5,-2.5) U4(-4,-2.5) U20(4,-2.5) U21(4.5,-2.5) U22(5,-2.5) U23(5.5,-2.5) V2(-5,-3) V3(-4.5,-3) V4(-4,-3) V20(4,-3) V21(4.5,-3) V22(5,-3) W1(-5.5,-3.5) W2(-5,-3.5) W3(-4.5,-3.5) W4(-4,-3.5) W20(4,-3.5) W21(4.5,-3.5) W22(5,-3.5) W23(5.5,-3.5) Y1(-5.5,-4) Y2(-5,-4) Y3(-4.5,-4) Y4(-4,-4) Y5(-3.5,-4) Y6(-3,-4) Y7(-2.5,-4) Y8(-2,-4) Y9(-1.5,-4) Y10(-1,-4) Y11(-0.5,-4) Y12(0,-4) Y13(0.5,-4) Y14(1,-4) Y15(1.5,-4) Y16(2,-4) Y17(2.5,-4) Y18(3,-4) Y19(3.5,-4) Y20(4,-4) Y21(4.5,-4) Y22(5,-4) Y23(5.5,-4)
  silkscreen extent -6.25,-6.07 6.07,6.25, body extent -6.07,-6.07 6.07,6.07, height 1.21
ICC_WFBGA134_SDP-SAC302_10X11P5_P065 [mm] "IPC"
  round 0.3 smd mask+0.05: A1(-2.925,5.2) A2(-2.275,5.2) A9(2.275,5.2) A10(2.925,5.2) B1(-2.925,4.55) B2(-2.275,4.55) B3(-1.625,4.55) B5(-0.325,4.55) B6(0.325,4.55) B7(0.975,4.55) B8(1.625,4.55) B9(2.275,4.55) B10(2.925,4.55) C1(-2.925,3.9) C2(-2.275,3.9) C3(-1.625,3.9) C5(-0.325,3.9) C6(0.325,3.9) C7(0.975,3.9) C8(1.625,3.9) C9(2.275,3.9) C10(2.925,3.9) D1(-2.925,3.25) D2(-2.275,3.25) D3(-1.625,3.25) D5(-0.325,3.25) D6(0.325,3.25) D7(0.975,3.25) D8(1.625,3.25) D9(2.275,3.25) D10(2.925,3.25) E1(-2.925,2.6) E2(-2.275,2.6) E3(-1.625,2.6) E5(-0.325,2.6) E6(0.325,2.6) E7(0.975,2.6) E8(1.625,2.6) E9(2.275,2.6) E10(2.925,2.6) F1(-2.925,1.95) F2(-2.275,1.95) F3(-1.625,1.95) F5(-0.325,1.95) F6(0.325,1.95) F7(0.975,1.95) F8(1.625,1.95) F9(2.275,1.95) F10(2.925,1.95) G1(-2.925,1.3) G2(-2.275,1.3) G3(-1.625,1.3) G5(-0.325,1.3) G6(0.325,1.3) G7(0.975,1.3) G8(1.625,1.3) G9(2.275,1.3) G10(2.925,1.3) H1(-2.925,0.65) H2(-2.275,0.65) H3(-1.625,0.65) H5(-0.325,0.65) H6(0.325,0.65) J1(-2.925,0) J2(-2.275,0) J3(-1.625,0) J5(-0.325,0) J6(0.325,0) J7(0.975,0) J8(1.625,0) J9(2.275,0) K1(-2.925,-0.65) K2(-2.275,-0.65) K3(-1.625,-0.65) K5(-0.325,-0.65) K6(0.325,-0.65) L1(-2.925,-1.3) L2(-2.275,-1.3) L3(-1.625,-1.3) L5(-0.325,-1.3) L6(0.325,-1.3) L7(0.975,-1.3) L8(1.625,-1.3) L9(2.275,-1.3) L10(2.925,-1.3) M1(-2.925,-1.95) M2(-2.275,-1.95) M3(-1.625,-1.95) M5(-0.325,-1.95) M6(0.325,-1.95) M7(0.975,-1.95) M8(1.625,-1.95) M9(2.275,-1.95) M10(2.925,-1.95) N1(-2.925,-2.6) N2(-2.275,-2.6) N3(-1.625,-2.6) N5(-0.325,-2.6) N6(0.325,-2.6) N7(0.975,-2.6) N8(1.625,-2.6) N9(2.275,-2.6) N10(2.925,-2.6) P1(-2.925,-3.25) P2(-2.275,-3.25) P3(-1.625,-3.25) P5(-0.325,-3.25) P6(0.325,-3.25) P7(0.975,-3.25) P8(1.625,-3.25) P9(2.275,-3.25) P10(2.925,-3.25) R1(-2.925,-3.9) R2(-2.275,-3.9) R3(-1.625,-3.9) R5(-0.325,-3.9) R6(0.325,-3.9) R7(0.975,-3.9) R8(1.625,-3.9) R9(2.275,-3.9) R10(2.925,-3.9) T1(-2.925,-4.55) T2(-2.275,-4.55) T3(-1.625,-4.55) T5(-0.325,-4.55) T6(0.325,-4.55) T7(0.975,-4.55) T8(1.625,-4.55) T9(2.275,-4.55) T10(2.925,-4.55) U1(-2.925,-5.2) U2(-2.275,-5.2) U9(2.275,-5.2) U10(2.925,-5.2)
  silkscreen extent -5.97,-5.8 5.05,5.8, body extent -5.05,-5.8 5.05,5.8, height 0.76
ICC_WFQFN44-EPAD_5X6_P040 [mm]
  rect 0.8x0.2 smd mask+0.05: 1(-2.45,2.2) 2(-2.45,1.8) 3(-2.45,1.4) 4(-2.45,1) 5(-2.45,0.6) 6(-2.45,0.2) 7(-2.45,-0.2) 8(-2.45,-0.6) 9(-2.45,-1) 10(-2.45,-1.4) 11(-2.45,-1.8) 12(-2.45,-2.2) 23(2.45,-2.2) 24(2.45,-1.8) 25(2.45,-1.4) 26(2.45,-1) 27(2.45,-0.6) 28(2.45,-0.2) 29(2.45,0.2) 30(2.45,0.6) 31(2.45,1) 32(2.45,1.4) 33(2.45,1.8) 34(2.45,2.2)
  rect 0.2x0.8 smd mask+0.05: 13(-1.8,-2.95) 14(-1.4,-2.95) 15(-1,-2.95) 16(-0.6,-2.95) 17(-0.2,-2.95) 18(0.2,-2.95) 19(0.6,-2.95) 20(1,-2.95) 21(1.4,-2.95) 22(1.8,-2.95) 35(1.8,2.95) 36(1.4,2.95) 37(1,2.95) 38(0.6,2.95) 39(0.2,2.95) 40(-0.2,2.95) 41(-0.6,2.95) 42(-1,2.95) 43(-1.4,2.95) 44(-1.8,2.95)
  rect 3.6x4.6 smd paste-1.8 mask+0.05: ep(0,0)
  silkscreen extent -2.5,-3 2.5,3, body extent -2.5,-3 2.5,3, height 0.81
IND_2520_TOKO_DFE252012P [mm]
  rect 0.8x2 smd mask+0.05: 1(-1,0) 2(1,0)
  silkscreen extent -1.35,-1.12 1.35,1.12, body extent -1.35,-1.1 1.35,1.1, height 2
R0402 [mm]
  rect 0.51x0.7 smd mask+0.05: 1(-0.45,0) 2(0.45,0)
  silkscreen extent 0,-0.3 0,0.3, body extent -0.52,-0.3 0.52,0.3, height 0.4
SWI_JIUBABA_C-TS-02H-2-5-B-V-T_R_BLUE [mm] "BLUE"
  rect 0.75x1 smd mask+0.05: 1(-2.225,0.75) 2(2.225,0.75) 3(-2.225,-0.75) 4(2.225,-0.75)
  silkscreen extent -1.85,-1.6 1.85,1.6, body extent -2.45,-1.6 2.45,1.6, height 2.6

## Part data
B1: library part MCD-00172, "Switch HW SMD blue", Manufacturer=JIUBABA, Manufacturer_Part_Number="C-TS-02H-2.5-B-V-T/R BLUE"
C1 C2 C3 C4 C5 C6 C7 C8 C9 C10 C11 C12 C17 C25 C26 C61 C66 C71 C78 C80 C82: library part MCD-00006, "Capacitor, MLCC, 100nF, 16V, X7R, 10%, 0402, T=0.5mm", Alternate_Manufacturer=MURATA, Alternate_Manufacturer_Part_Number=GCM155R71C104KA55D, Manufacturer=YAGEO, Manufacturer_Part_Number=CC0402KRX7R7BB104, Package=C0402
C15 C16: library part MCD-01124, "Capacitor, MLCC, 10uF, 10V, X5R, 10%, 0603, T=0.8mm", Manufacturer=MURATA, Manufacturer_Part_Number=GRM188R61A106KAAL, Package=C0603
C18 C31 C33 C39 C42 C46: library part MCD-00099, "Capacitor, MLCC, 10uF, 10V, X5R, 10%, 0603, T=0,8mm", Manufacturer=MURATA, Manufacturer_Part_Number=GRM188R61A106KE69D, Package=C0603
C29 C34 C38 C40: library part MCD-00100, "Capacitor, MLCC, 22uF, 6V3, X5R, 20%, 0603, T=0,8mm", Manufacturer=MURATA, Manufacturer_Part_Number=GRM188R60J226MEA0J, Package=C0603
C30 C32 C35 C36 C37 C41 C45 C47 C48 C50 C53 C54 C55 C70 C75 C76 C77 C84 C92 C94 C95 C96: library part MCD-00095, "Capacitor, MLCC, 1uF, 25V, X5R, 10%, 0402, T=0,5mm", Alternate_Manufacturer=MURATA, Alternate_Manufacturer_Part_Number=GRM155R60J105KE19, Manufacturer_Part_Number=GRM155R61E105KA12, Package=C0402
C43 C49 C51 C52: library part MCD-00096, "Capacitor, MLCC, 4.7uF, 6V3, X5R, 20%, 0402, T=0,5mm", Manufacturer=MURATA, Manufacturer_Part_Number=GRM155R60J475ME87, Package=C0402
C44 C58: library part MCD-00011, "Capacitor, MLCC, 10nF, 16V, X7R, 10%, 0402, T=0.5mm", Manufacturer=YAGEO, Manufacturer_Part_Number=CC0402KRX7R7BB103, Package=C0402
C56 C57: library part MCD-01508, "Capacitor, MLCC, 820pF, 50V, X7R, 10%, 0402, T=0.55mm", Manufacturer=YAGEO, Manufacturer_Part_Number=CC0402KRX7R9BB821, Package=C0402
C67 C68 C69: library part MCD-01823, "Capacitor,MLCC,2.2uF,6V3,X5R,10%,0402,T=0.5", Manufacturer=MURATA, Manufacturer_Part_Number=GRM155R60J225KE95D, Package=C0402
C79 C81 C83: library part MCD-00012, "Capacitor, MLCC, 2.2uF, 10V, X5R, 10%, 0603, T=0,8mm", Alternate_Manufacturer=KEMET, Alternate_Manufacturer_Part_Number=C0603C225K8PACTU, Manufacturer=YAGEO, Manufacturer_Part_Number=CC0603KRX5R6BB225, Package=C0603
L1 L2 L3 L4: library part MCD-01122, "Power Inductor ,1uH,4.3A max,+/-20%,0.042ohm,2520", Manufacturer=MURATA, Manufacturer_Part_Number=DFE252012P-1ROM{}P2, Package=2520
R14: library part MCD-00067, "Resistor,100R,0402,1%,1/16W", Manufacturer=YAGEO, Manufacturer_Part_Number=RC0402FR-07100RL, Package=R0402
R26 R40: library part MCD-00053, "Resistor,10K,0402,1%,1/16W", Manufacturer=YAGEO, Manufacturer_Part_Number=RC0402FR-0710KL, Package=R0402
R27 R29: library part MCD-00120, "Resistor,240R,0402,1%,1/16W", Manufacturer=YAGEO, Manufacturer_Part_Number=RC0402FR-07240RL, Package=R0402
R37 R38: library part MCD-00068, "Resistor,1K5,0402,1%,1/16W", Manufacturer=YAGEO, Manufacturer_Part_Number=RC0402FR-071K5L, Package=R0402
R41: library part MCD-00052, "Resistor,0R,0402,5%,1/16W", Manufacturer=YAGEO, Manufacturer_Part_Number=RC0402JR-070RL, Package=R0402
R43: library part MCD-00063, "Resistor,47K,0402,1%,1/16W", Manufacturer=YAGEO, Manufacturer_Part_Number=RC0402FR-0747KL, Package=R0402
U1: library part MCD-00677, "MPU TFBGA12x12 secure boot+crypto", Manufacturer=STMICROELECTRONICS, Manufacturer_Part_Number=STM32MP157CAC3
U2: library part MCD-01223, "Memory,LPDDR2,4Gb,128Mbx32,533MHz,1066Mb/s,1V8/1V2,FBGA134", Manufacturer=MICRON, Manufacturer_Part_Number=EDB4432BBBJ-1D-F-R, Package="WFBGA134 10x11.5"
U4: library part MCD-00303, "STM PMIC WFQFN 5.0x6.0x0.80 44L 0.4 pitch", Manufacturer=STMICROELECTRONICS, Manufacturer_Part_Number=STPMU1APQR
U5: library part MCD-00110, "Memory,e-MMC,4GB,3V3,WFBGA,153pins", Manufacturer=TOSHIBA, Manufacturer_Part_Number=THGBMDG5D1LBAIL

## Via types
v1: diameter 0.4, hole 0.2, Top Layer to Bottom Layer, tented both sides, 265 vias
v2: diameter 0.6, hole 0.3, Top Layer to Bottom Layer, tented both sides, 102 vias
v3: diameter 0.25, hole 0.1, Top Layer to Signal Layer 1, tented top, 82 vias
v4: diameter 0.25, hole 0.1, Top Layer to Signal Layer 1, tented both sides, 5 vias

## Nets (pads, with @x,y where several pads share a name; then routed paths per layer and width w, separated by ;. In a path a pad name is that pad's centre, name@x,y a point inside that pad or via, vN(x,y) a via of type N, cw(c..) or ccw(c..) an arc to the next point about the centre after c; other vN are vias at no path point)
3V3: C32.2 C40.2 C78.2 C79.2 L4.2 U4.22 U4.27 U5.E6 U5.F5 U5.J10 U5.K9 | length 50.8
  Top Layer w0.1: v3(12.25,81.45) U4.27@12.25,82.025
  Top Layer w0.175: U5.J10@27.7,88.475 U5.K9@28.2,88.975 v1(28.2,89.45) ; U5.E6@29.7,86.475 U5.F5@30.2,86.975 v1(30.625,86.975)
  Top Layer w0.2: 9.725,82.5 U4.22@9.9,82.675 9.9,82.491
  Top Layer w0.3: 9.625,82.5 9.725,82.5
  Top Layer w0.4: C32.2@7.7,80.075 7.9,80.075 8.187,80.362 8.635,80.81 8.635,81.41 9.725,82.5
  Signal Layer 1 w0.2: v2(11.575,74.9) 12.25,75.575 v3(12.25,81.45)
  Signal Layer 4 w0.3: v2(8.3,80.25) 7.225,79.175 7.225,76.825 9.15,74.9 v2(10.2,74.9) v2(10.9,74.9) v2(11.575,74.9)
  Bottom Layer w0.13: C78.2@30.025,86.9 C78.2@30.125,87 ; v1@30.6,87 v1(30.625,86.975)
  Bottom Layer w0.3: v2(11.575,74.9) 17.275,80.6 17.275,82.625 18.775,84.125 22.575,84.125 25.25,86.8 25.25,87.475 C79.2@27.35,89.575 ; C79.2@27.475,89.45 28.175,89.45 28.188,89.437 29.325,88.3 29.325,87.6 C78.2@30.025,86.9 ; C78.2@30.125,87 v1@30.6,87
5V_VIN: C18.2 C31.2 C33.2 C39.2 C41.2 C51.2 R43.2 U4.8 U4.12 U4.19 U4.24 U4.28 U4.36 U4.37 | length 20.5
  Top Layer w0.2: 8.775,83.875 U4.19@9.9,83.875 ; 11.05,81.3 U4.24@11.05,82.025 ; U4.8@12.25,86.925 12.25,88.76 ; U4.28@12.65,82.025 12.65,80.975 13.625,80 C31.2@13.625,79.25 ; U4.36@15.8,83.075 16.45,83.075 C51.2@16.7,82.825 ; U4.37@15.8,83.475 16.825,83.475
  Top Layer w0.3: C41.2@7.7,83.325 8.25,83.875 8.775,83.875 ; v1(8.075,78.775) v1(8.55,78.775) v1(9,78.775) ; v2(18.575,81.45) 19.325,81.45 R43.2@19.461,81.586
  Top Layer w0.4: v2(4.725,83.15) v2(5.35,83.15) 5.735,82.765 7.335,82.765 7.7,83.13 C41.2@7.7,83.325
  Top Layer w0.45: 16.625,83.55 18.078,83.55 18.503,83.125 v2(18.575,83.125) ; C51.2@16.7,82.825 16.7,82.127 17.377,81.45 v2(18.575,81.45)
  other v1: 13.225,78.725 13.725,78.725 14.2,78.725
  other v2: 6.075,88.575 6.075,89.2 6.075,89.825 11.85,89.9 12.55,89.9
DDR_A0: U1.L20 U2.P3 | length 19.7
  Top Layer w0.12: v1@35.605,62.95 35.605,62.998 35.807,63.2 U1.L20@36,63.2 ; v1(49.57,65.07) 49.57,65.145 U2.P3@50.059,65.634
  Bottom Layer w0.12: v1(35.625,62.95) 35.961,63.286 36.127,63.286 37.031,64.19 37.031,65.336 38.835,67.14 43.749,67.14 44.074,66.815 44.074,66.522 44.426,66.17 44.843,66.17 45.055,66.383 45.055,66.759 45.436,67.14 45.806,67.14 46.4,66.546 47.199,66.546 ; 47.205,66.541 48.674,65.072 49.57,65.072 v1@49.572,65.072
DDR_A1: U1.P22 U2.N3 | length 19.5
  Top Layer w0.1: v1(35.625,61.95) 36.75,61.95 U1.P22@37,61.7
  Top Layer w0.12: v1@49.605,64.22 49.605,64.555 U2.N3@50.05,65
  Bottom Layer w0.12: v1(35.625,61.95) 35.654,61.95 37.222,63.517 37.222,63.647 40.131,66.557 42.058,66.557 44.362,64.253 47.97,64.253 48.154,64.437 49.373,64.437 v1@49.583,64.227
  other v1: 49.6,64.22
DDR_A2: U1.J20 U2.M3 | length 19
  Top Layer w0.12: v1@35.75,63.95 U1.J20@36,64.2 ; U2.M3@50.085,64.35 50.375,64.64 v1(50.375,65.325)
  Bottom Layer w0.12: v1(35.65,63.95) 35.7,63.95 36.578,64.828 36.578,65.477 38.678,67.577 45.963,67.577 46.58,66.96 47.38,66.96 48.848,65.492 49.917,65.492 50.081,65.329 v1@50.374,65.329
DDR_A3: U1.K22 U2.M2 | length 19.5
  Top Layer w0.1: U1.K22@37,63.7 37.25,63.45 37.94,63.45
  Top Layer w0.12: 37.94,63.45 v1@38.17,63.22 ; v1@50.346,64.017 50.364,64.036 U2.M2@50.678,64.35
  Signal Layer 3 w0.127: v1@38.167,63.193 38.167,63.2 38.167,66.647 38.593,67.074 46.063,67.074 46.182,66.954 46.857,66.954 48.368,65.443 49.822,65.443 49.999,65.267 49.999,65.074 50.372,64.701 50.372,64.025 v1@50.372,64.018
  other v1: 38.17,63.2 50.375,64.025
DDR_A4: U1.V20 U2.M1 | length 17.9
  Top Layer w0.12: v1@35.677,59.949 35.739,59.949 U1.V20@35.988,59.7 ; v1@51.031,64.031 U2.M1@51.35,64.35
  Bottom Layer w0.12: v1@35.662,59.952 36.206,59.952 39.13,62.876 41.186,62.876 41.557,63.247 50.252,63.247 ; 50.254,63.246 51.029,64.021 v1@51.033,64.025
  other v1: 35.66,59.95 51.025,64.025
DDR_A5: U1.H20 U2.G2 | length 18.3
  Top Layer w0.12: v1@35.645,64.43 35.67,64.455 35.915,64.7 U1.H20@36,64.7 ; v1@50.37,60.77 v1(50.375,60.775) U2.G2@50.7,61.1
  Signal Layer 3 w0.127: v1@35.654,64.475 36.777,63.352 36.777,62.946 38.758,60.965 44.173,60.965 ; 44.174,60.965 45.045,60.094 45.348,60.094 45.939,60.685 46.981,60.685 47.327,60.685 47.661,60.351 49.95,60.351 v1(50.375,60.775) v1@50.378,60.779
  other v1: 35.65,64.475
DDR_A6: U1.W20 U2.F2 | length 17
  Top Layer w0.12: v1@35.3,59.59 35.645,59.59 U1.W20@36,59.235 ; v1@50.38,60.13 U2.F2@50.7,60.45
  Bottom Layer w0.12: v1@35.302,59.592 35.304,59.59 38.208,59.59 38.381,59.417 45.792,59.417 46.867,60.492 47.92,60.492 48.011,60.402 49.528,60.402 49.792,60.137 v1@50.367,60.137
  other v1: 35.285,59.605 50.375,60.125
DDR_A7: U1.E20 U2.F3 | length 17.8
  Top Layer w0.12: v1@35.6,65.968 35.832,66.2 U1.E20@36,66.2 ; v1@49.727,60.772 U2.F3@50.05,60.45
  Signal Layer 3 w0.127: v1@35.606,65.938 37.342,64.202 ; 37.345,64.199 37.345,63.371 39.11,61.605 47.431,61.605 47.615,61.789 48.703,61.789 v1@49.721,60.771
  other v1: 49.725,60.775 35.6,65.945
DDR_A8: U1.Y20 U2.E3 | length 16.5
  Top Layer w0.12: v1(35.585,59.13) U1.Y20@36,58.715 ; v1(49.725,59.475) U2.E3@50.05,59.8
  Bottom Layer w0.12: v1@35.587,59.132 35.807,58.912 37.277,58.912 37.502,58.687 41.392,58.687 41.882,58.192 42.482,58.192 42.977,58.687 45.707,58.687 46.402,59.382 47.129,59.382 47.589,59.842 48.528,59.842 48.668,59.982 49.229,59.982 v1@49.731,59.481
DDR_A9: U1.G20 U2.E2 | length 19.6
  Top Layer w0.12: v1(35.65,64.975) 35.775,64.975 U1.G20@36,65.2 ; v1(50.375,59.475) U2.E2@50.7,59.8
  Signal Layer 3 w0.127: 35.499,64.838 35.287,64.626 35.266,64.604 35.266,63.735 35.563,63.438 35.654,63.438 36.35,62.742 36.35,62.478 39.319,59.509 47.151,59.509 ; 35.5,64.838 v1@35.639,64.977 ; 47.15,59.508 47.482,59.84 49.999,59.84 50.369,59.469 v1@50.371,59.467
DDR_CKE: R26.2 U1.T20 U2.K1 | length 21.5
  Top Layer w0.12: v1(35.65,60.935) 35.765,60.935 U1.T20@36,60.7 ; v1(49.6,63.644) 49.904,63.34 51.067,63.34 U2.K1@51.343,63.063 ; U2.K1@51.35,63.05 53.421,63.05 53.766,63.394 R26.2@54.816,63.394
  Bottom Layer w0.12: v1(35.65,60.935) 36.48,61.765 36.48,62.02 38.023,63.562 38.418,63.562 38.744,63.236 39.488,63.236 39.667,63.415 41.131,63.415 41.383,63.667 ; 41.383,63.665 v1@49.6,63.665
